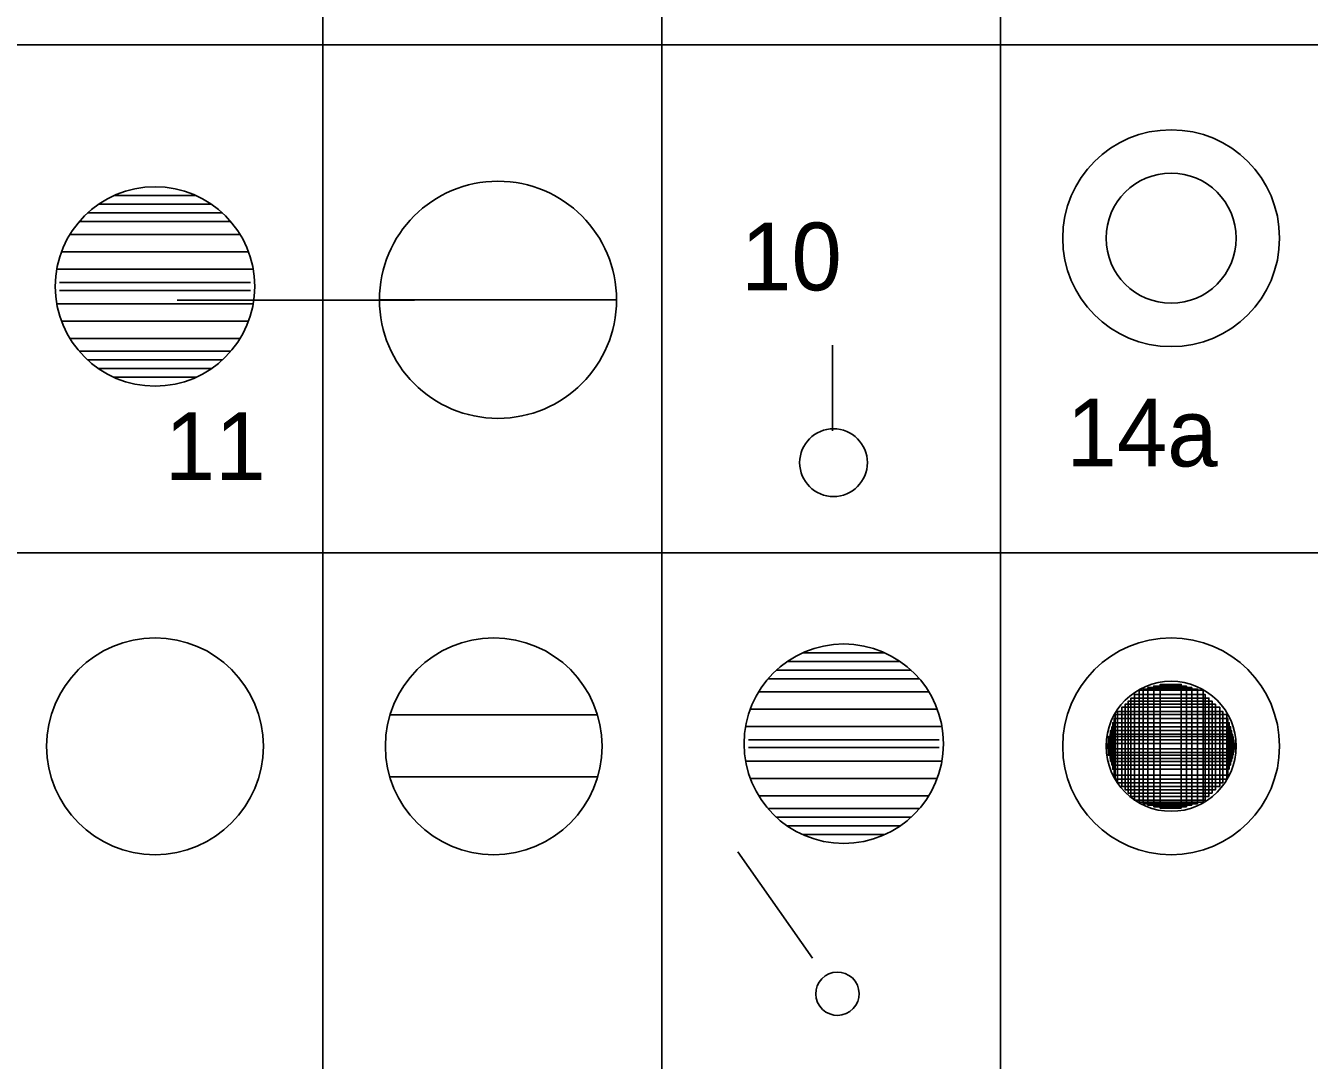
# Model space of a CAD drawing. Extents: x -28 to 822, y 61 to 665.
# Drawn here: x 361.84 to 399.74, y 246.76 to 277.3 of the extents above; entities that cross this region are included whole.
import ezdxf

# ---------------------------------------------------------------- set-up
doc = ezdxf.new("R2010")
doc.units = 0
doc.layers.add('KOLEJIŠTĚ', color=7, linetype='Continuous')

# ---------------------------------------------------------------- blocks, each defined once
blk = doc.blocks.new('HR6')
for p, q in [((-0.95, 2.095), (0.95, 2.095)), ((-1.304, 1.895), (1.304, 1.895)), ((-1.748, 1.495), (1.748, 1.495)), ((-1.555, 1.695), (1.555, 1.695)), ((-1.962, 1.2), (1.962, 1.2)), ((-2.156, 0.8), (2.156, 0.8)), ((-2.265, 0.4), (2.265, 0.4)), ((-2.2, 0.09), (2.2, 0.09)), ((-2.2, -0.09), (2.2, -0.09)), ((-2.265, -0.4), (2.265, -0.4)), ((-2.156, -0.8), (2.156, -0.8)), ((-1.962, -1.2), (1.962, -1.2)), ((-1.748, -1.495), (1.748, -1.495)), ((-1.555, -1.695), (1.555, -1.695)), ((-1.304, -1.895), (1.304, -1.895)), ((-0.95, -2.095), (0.95, -2.095))]:
    blk.add_line(p, q)
for start, end in [(0, 180), (180, 0)]:
    blk.add_arc((0, 0), 2.3, start, end)
blk = doc.blocks.new('ZT75')
at = {"xscale": 0.8, "yscale": 0.8000000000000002}
blk.add_blockref('HR6', (0, 0), dxfattribs=at)
blk = doc.blocks.new('HR3')
for radius in [2.5, 1.5]:
    blk.add_circle((0, 0), radius)
blk = doc.blocks.new('ZT72')
at = {"xscale": 0.8, "yscale": 0.8000000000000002}
blk.add_blockref('HR3', (0, 0), dxfattribs=at)
blk = doc.blocks.new('HR1')
blk.add_line((-2.5, 0), (2.5, 0))
blk.add_circle((0, 0), 2.5)

msp = doc.modelspace()

# ---------------------------------------------------------------- linework, layer by layer
for p, q in [((370.616, 381.738), (370.616, 111.738)), ((380.616, 381.738), (380.616, 111.738)), ((390.616, 381.738), (390.616, 111.738)), ((339.087, 276.738), (540.616, 276.738)), ((373.317, 269.202), (366.312, 269.202)), ((385.657, 265.34), (385.657, 267.872)), ((5.068, 261.738), (540.616, 261.738)), ((378.72, 256.957), (372.594, 256.957)), ((378.727, 255.126), (372.588, 255.126)), ((382.868, 252.92), (385.071, 249.774))]:
    msp.add_line(p, q)
for points in [[(396.437, 254.337), (394.826, 254.337), (394.826, 257.719), (396.437, 257.719)], [(396.264, 254.292), (394.972, 254.292), (394.972, 257.765), (396.264, 257.765)], [(396.109, 254.246), (395.145, 254.246), (395.145, 257.81), (396.109, 257.81)], [(395.955, 254.201), (395.336, 254.201), (395.336, 257.856), (395.955, 257.856)], [(396.865, 254.646), (394.39, 254.646), (394.39, 257.365), (396.865, 257.365)], [(396.774, 254.546), (394.471, 254.546), (394.471, 257.456), (396.774, 257.456)], [(396.665, 254.437), (394.572, 254.437), (394.572, 257.556), (396.665, 257.556)], [(396.601, 254.383), (394.708, 254.383), (394.708, 257.692), (396.601, 257.692)], [(397.302, 255.064), (394.007, 255.064), (394.007, 256.965), (397.302, 256.965)], [(397.183, 254.955), (394.071, 254.955), (394.071, 257.056), (397.183, 257.056)], [(397.092, 254.846), (394.198, 254.846), (394.198, 257.183), (397.092, 257.183)], [(396.965, 254.746), (394.299, 254.746), (394.299, 257.274), (396.965, 257.274)], [(397.411, 255.474), (393.907, 255.474), (393.907, 256.61), (397.411, 256.61)], [(397.374, 255.355), (393.935, 255.355), (393.935, 256.728), (397.374, 256.728)], [(397.329, 255.183), (393.971, 255.183), (393.971, 256.847), (397.329, 256.847)], [(397.484, 255.765), (393.807, 255.765), (393.807, 256.319), (397.484, 256.319)], [(397.511, 255.846), (393.807, 255.846), (393.807, 256.219), (397.511, 256.219)], [(397.465, 255.674), (393.853, 255.674), (393.853, 256.392), (397.465, 256.392)], [(397.438, 255.583), (393.871, 255.583), (393.871, 256.501), (397.438, 256.501)], [(397.547, 255.956), (393.78, 255.956), (393.78, 256.11), (397.547, 256.11)]]:
    msp.add_lwpolyline(points, close=True)
for centre, radius in [((385.689, 264.404), 1), ((365.657, 256.031), 3.2), ((375.657, 256.031), 3.2)]:
    msp.add_circle(centre, radius)
for start, end in [(35, 215), (215, 35)]:
    msp.add_arc((385.805, 248.726), 0.64, start, end)

# ---------------------------------------------------------------- block references
at = {"xscale": 1.4000000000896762, "yscale": 1.4000000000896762}
msp.add_blockref('HR1', (375.783, 269.212), dxfattribs=at)
at = {"layer": 'KOLEJIŠTĚ', "xscale": 1.600000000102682, "yscale": 1.600000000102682}
for name, p in [('ZT72', (395.657, 271.031)), ('ZT75', (365.657, 269.606)), ('ZT72', (395.657, 256.031)), ('ZT75', (385.991, 256.107))]:
    msp.add_blockref(name, p, dxfattribs=at)

# ---------------------------------------------------------------- texts
for s, p in [('10', (382.959, 269.491)), ('14a', (392.566, 264.292)), ('11', (365.947, 263.892))]:
    msp.add_text(s, height=2).set_placement(p)

doc.saveas('drawing.dxf')
